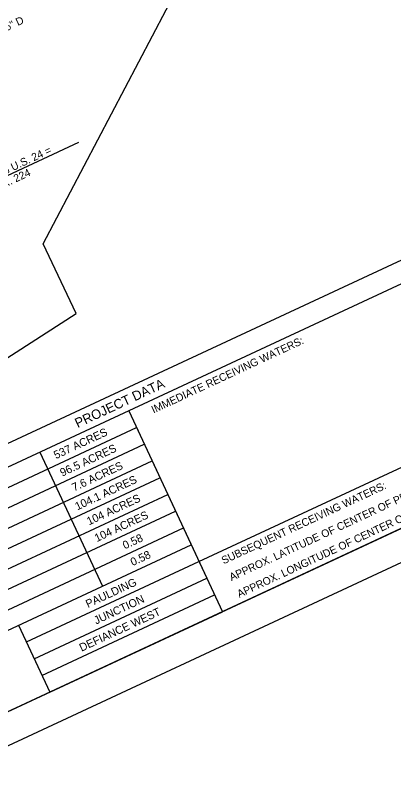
# Model space of a CAD drawing. Extents: x -310467766 to 17062430, y -322263100 to 8322522.
# Drawn here: x 1399466 to 1401306, y 570590 to 574364 of the extents above; entities that cross this region are included whole.
import ezdxf

# ---------------------------------------------------------------- set-up
doc = ezdxf.new("R2010")
doc.units = 0
for name, color, linetype in [('Level 40', 7, 'Continuous'), ('SC_Scratch1', 7, 'Continuous'), ('SH_Border', 7, 'Continuous'), ('SH_Cut_Line', 7, 'Continuous')]:
    doc.layers.add(name, color=color, linetype=linetype)

msp = doc.modelspace()

# ---------------------------------------------------------------- linework, layer by layer
at = {"layer": 'Level 40'}
for p, q in [((1399053.9, 573411.1), (1399774.6, 573747.2)), ((1397552.3, 571405.7), (1402393.6, 573663.2)), ((1397596.7, 571310.5), (1402438, 573568)), ((1400359.6, 571705.1), (1402780.3, 572833.9)), ((1398053.1, 570331.7), (1402894.4, 572589.2)), ((1400017.3, 572439.3), (1400473.8, 571460.4)), ((1400017.3, 572439.3), (1400397.7, 571623.6)), ((1397634.7, 571228.9), (1400055.4, 572357.7)), ((1397672.8, 571147.4), (1400093.4, 572276.1)), ((1399585.3, 572237.8), (1399889.6, 571585.3)), ((1397710.8, 571065.8), (1400131.4, 572194.6)), ((1397748.8, 570984.2), (1400169.5, 572113)), ((1397786.9, 570902.7), (1400207.5, 572031.4)), ((1397824.9, 570821.1), (1400245.5, 571949.9)), ((1397862.9, 570739.5), (1400283.6, 571868.3)), ((1397901, 570658), (1400321.6, 571786.7)), ((1397901, 570658), (1400321.6, 571786.7)), ((1399519.2, 571313.2), (1400359.6, 571705.1)), ((1399557.2, 571231.7), (1400397.7, 571623.6)), ((1399595.3, 571150.1), (1400435.7, 571542)), ((1399633.3, 571068.5), (1400473.8, 571460.4)), ((1399481.2, 571394.8), (1399633.3, 571068.5))]:
    msp.add_line(p, q, dxfattribs=at)
at = {"layer": 'SC_Scratch1'}
msp.add_lwpolyline([(1392212.4, 573822.1), (1393676.3, 570715.4), (1396857.5, 571041.4), (1399761.2, 572912.7), (1399601.4, 573251.9), (1400998.4, 575913.7), (1400551.7, 577289.3)], close=True, dxfattribs=at)
at = {"layer": 'SH_Border'}
msp.add_lwpolyline([(1391939.2, 574432), (1400639.7, 578489.1), (1403302.2, 572779.4), (1394601.7, 568722.3)], close=True, dxfattribs=at)
at = {"layer": 'SH_Cut_Line'}
msp.add_lwpolyline([(1394257.2, 568396.1), (1403501.6, 572706.8), (1400712.3, 578688.5), (1391467.9, 574377.8)], close=True, dxfattribs=at)

# ---------------------------------------------------------------- texts
at = {"layer": 'Level 40'}
for s, height, p in [('15" D', 37.5, (1399398.8, 574276.2)), ('STA. 1404+15.26 U.S. 24 =', 37.5, (1399086.6, 573435.4)), ('STA. 50+00 C.R. 224', 37.5, (1399110.4, 573384.4)), ('IMMEDIATE RECEIVING WATERS:', 37.5, (1400138.3, 572425.4)), ('PROJECT DATA', 46.5, (1399768.6, 572354.9)), ('537 ACRES', 39, (1399663.5, 572203.1)), ('96.5 ACRES', 39, (1399694.1, 572118)), ('7.6 ACRES', 39, (1399751.9, 572045.7)), ('104.1 ACRES', 39, (1399767.2, 571953.6)), ('APPROX. LATITUDE OF CENTER OF PROJECT:', 37.5, (1400517.7, 571609.3)), ('SUBSEQUENT RECEIVING WATERS:', 37.5, (1400479.7, 571690.9)), ('104 ACRES', 39, (1399824.2, 571880.8)), ('APPROX. LONGITUDE OF CENTER OF PROJECT:', 37.5, (1400555.8, 571527.7)), ('104 ACRES', 39, (1399862.2, 571799.2)), ('0.58', 39, (1399998.9, 571763.7)), ('0.58', 39, (1400036.9, 571682.1)), ('PAULDING', 39, (1399818.9, 571478.4)), ('JUNCTION', 39, (1399858.9, 571397.7)), ('DEFIANCE WEST', 39, (1399788.1, 571265.4))]:
    msp.add_text(s, height=height, rotation=25, dxfattribs=at).set_placement(p)

doc.saveas('drawing.dxf')
